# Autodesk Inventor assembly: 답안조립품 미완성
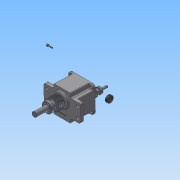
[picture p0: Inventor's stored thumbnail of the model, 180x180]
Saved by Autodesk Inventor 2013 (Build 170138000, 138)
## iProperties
Created: 2014-12
Part Number: 답안조립품 미완성
Document SubType Name: Assembly
Designer: Administrator
Author: Administrator
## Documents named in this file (11)
- C:\Users\Administrator\Desktop\Inventor2급-임성민\답안조립품 미완성.iam
- C:\Users\Administrator\Desktop\Inventor2급-임성민\본체.ipt
- C:\Users\Administrator\Desktop\Inventor2급-임성민\M4x0.5x16.ipt
- C:\Users\Administrator\Desktop\Inventor2급-임성민\메인축.ipt
- C:\Users\Administrator\Desktop\Inventor2급-임성민\베어링 608.ipt
- 베어링 608.ipt
- C:\Users\Administrator\Desktop\Inventor2급-임성민\베어링 6003.ipt
- 베어링 6003.ipt
- C:\Users\Administrator\Desktop\Inventor2급-임성민\서브축.ipt
- C:\Users\Administrator\Desktop\Inventor2급-임성민\오일실 8x22x7.ipt
- C:\Users\Administrator\Desktop\Inventor2급-임성민\오일실 17x32x8.ipt
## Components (1 placed, 1 different names)
1. M4x0.5x12:1
